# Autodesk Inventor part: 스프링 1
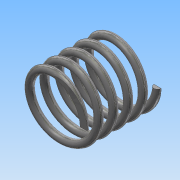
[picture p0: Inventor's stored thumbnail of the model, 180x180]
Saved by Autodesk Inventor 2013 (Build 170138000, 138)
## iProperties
Created: 2016-03
Part Number: 스프링 1
Material: 스테인리스강
Document SubType Name: Modeling
Designer: Administrator
Density: 8.08 g/cm^3
Mass: 6.63811 g
Surface Area: 16.7091 cm^2
Volume: 0.821548 cm^3
Author: Administrator
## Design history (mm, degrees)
sketch "스케치1"
  geometry: L1 (0, 0)-(8.5, 0); L2 (8.5, 20.5)-(0, 20.5); L3 (0, 20.5)-(0, 0); C1 r 1 at (8.5, 0)
  constraints: 6 end point, 2 parallel, 1 centre point, 1 coincident, 1 horizontal, 1 perpendicular
  dimensions: "d0" = 2 diameter of C1; "d1" = 17 diameter of C1.centre L3; "d2" = 20.5 distance between parallel lines of L1 L2 (derived)
feature "코일1" sketch "스케치1" pitch "d3" = 10; turns "d5" = 5; dims "d4" = 20.5 (= d2), "d6" = 0, angle "d7" = 90 deg, angle "d8" = 90 deg, "d9" = 0, "d10" = 0
sketch "스케치2"
  geometry: L1 (0, -15)-(20.5, -15); L2 (20.5, -15)-(20.5, 15); L3 (20.5, 15)-(0, 15); L4 (0, 15)-(0, -15); 2 further points
  constraints: 8 end point, 2 parallel, 1 coincident, 1 horizontal, 1 midpoint, 1 perpendicular
  dimensions: "d11" = 20.5 distance between parallel lines of L4 L2 (derived); "d13" = 30 distance of L1.end L2.end
extrude "돌출1" sketch "스케치2" stored distance "d14" = 0; taper "d15" = 0 deg
node "솔리드1"
